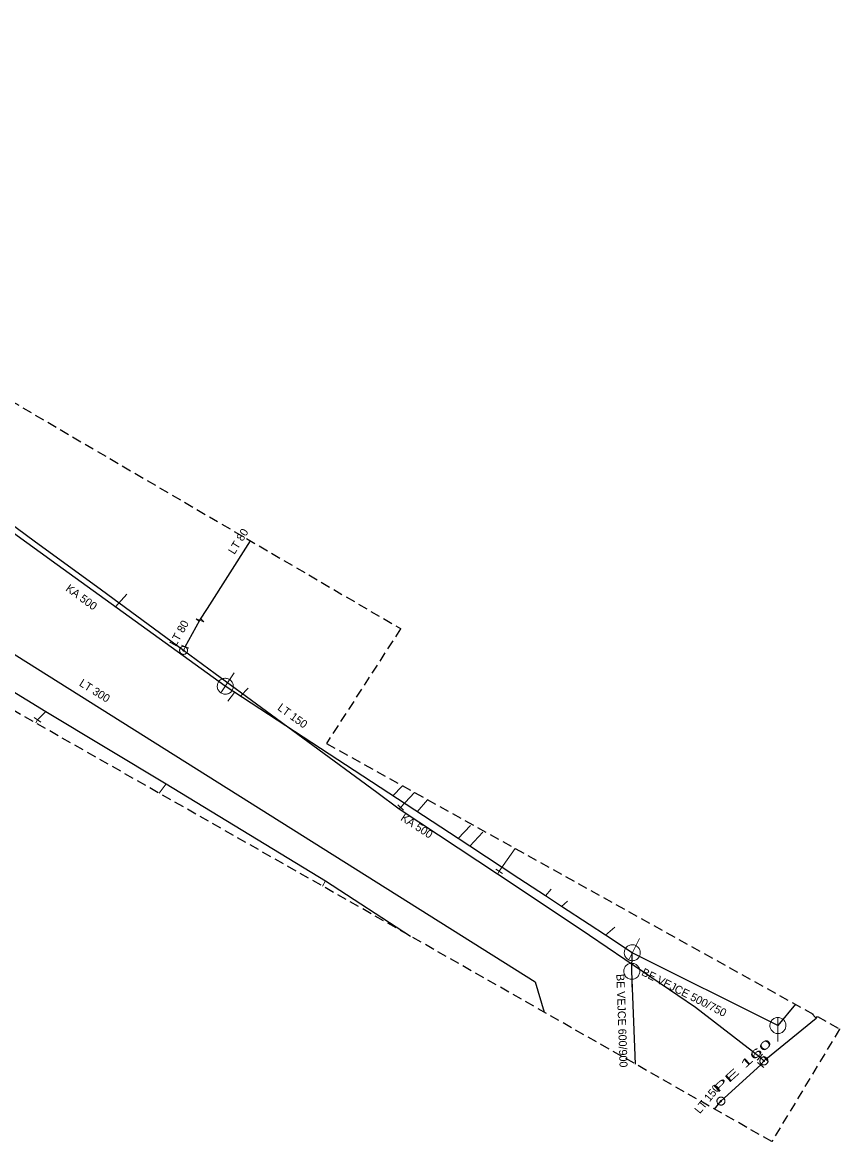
# Model space of a CAD drawing. Extents: x -747112 to -746911, y -964685 to -964545.
# Drawn here: x -747012.7 to -746910.6, y -964684.7 to -964544.9 of the extents above; entities that cross this region are included whole.
import ezdxf

# ---------------------------------------------------------------- set-up
doc = ezdxf.new("R2010")
doc.units = 0
doc.header["$LTSCALE"] = 0.4
doc.linetypes.add('MEDIUM_DASHED', pattern=[4.5, 3, -1.5])
doc.layers.add('1', color=7, linetype='Continuous')
for name, color, linetype, lineweight in [('11', 7, 'Continuous', 13), ('13', 7, 'Continuous', 13), ('14', 7, 'Continuous', 13), ('17', 7, 'Continuous', 25), ('22', 7, 'Continuous', 13), ('34', 7, 'Continuous', 13), ('47', 7, 'Continuous', 13), ('63', 7, 'MEDIUM_DASHED', 25)]:
    doc.layers.add(name, color=color, linetype=linetype, lineweight=lineweight)

msp = doc.modelspace()

# ---------------------------------------------------------------- linework, layer by layer
at = {"layer": '11'}
for p, q in [((-746999.699, -964616.359), (-747001.122, -964617.943)), ((-746987.074, -964629.717), (-746986.216, -964628.62)), ((-746984.513, -964628.107), (-746985.469, -964629.108)), ((-746965.289, -964640.322), (-746966.441, -964641.539)), ((-746962.113, -964642.035), (-746963.4, -964643.526)), ((-746956.714, -964645.237), (-746958.282, -964646.869)), ((-746955.19, -964646.083), (-746956.83, -964647.853)), ((-746946.636, -964653.223), (-746947.368, -964654.028)), ((-746944.605, -964654.714), (-746945.366, -964655.368)), ((-746938.691, -964657.953), (-746939.866, -964658.936))]:
    msp.add_line(p, q, dxfattribs=at)
at = {"layer": '13'}
for p, q in [((-747009.793, -964630.991), (-747010.845, -964632.051)), ((-747010.845, -964632.051), (-747011.081, -964632.441)), ((-746994.776, -964640.041), (-746995.644, -964641.216)), ((-746965.464, -964643.011), (-746963.723, -964641.11)), ((-746974.873, -964652.184), (-746975.215, -964652.828)), ((-746913.524, -964669.316), (-746914.114, -964668.705))]:
    msp.add_line(p, q, dxfattribs=at)
msp.add_lwpolyline([(-746953.369, -964651.351), (-746953.142, -964650.975), (-746951.129, -964648.115)], dxfattribs=at)
at = {"layer": '14'}
for p, q in [((-746992.592, -964623.377), (-746992.399, -964622.915)), ((-746965.631, -964643.226), (-746965.464, -964643.011)), ((-746920.058, -964674.663), (-746920.566, -964674.208)), ((-746920.058, -964674.663), (-746920.46, -964675.157)), ((-746919.813, -964674.445), (-746920.058, -964674.663))]:
    msp.add_line(p, q, dxfattribs=at)
at = {"layer": '14', "lineweight": 25}
for p, q in [((-746918.309, -964670.239), (-746936.511, -964661.149)), ((-746916.123, -964667.588), (-746918.309, -964670.239))]:
    msp.add_line(p, q, dxfattribs=at)
for points in [[(-746987.381, -964627.86), (-746994.138, -964622.982), (-747008.407, -964612.686), (-747020.272, -964604.125), (-747021.16, -964603.609), (-747024.27, -964601.239), (-747027.37, -964599.01), (-747029.581, -964597.407), (-747034.561, -964593.842), (-747037.631, -964591.6)], [(-746936.511, -964661.149), (-746939.866, -964658.936), (-746941.912, -964657.614), (-746945.366, -964655.368), (-746947.368, -964654.028), (-746950.693, -964651.868), (-746956.83, -964647.853), (-746958.282, -964646.869), (-746987.381, -964627.86)], [(-746936.099, -964675.063), (-746936.57, -964663.46), (-746936.511, -964661.149)]]:
    msp.add_lwpolyline(points, dxfattribs=at)
at = {"layer": '17'}
msp.add_line((-746992.399, -964622.915), (-746990.549, -964619.615), dxfattribs=at)
for points in [[(-746992.592, -964623.377), (-747002.848, -964615.868), (-747011.265, -964609.743), (-747020.612, -964602.861), (-747030.192, -964595.879), (-747034.92, -964592.421), (-747039.8, -964588.87), (-747041.949, -964584.539), (-747049.208, -964579.357)], [(-747058.793, -964595.589), (-747057.25, -964596.522), (-746948.662, -964664.784), (-746947.539, -964668.56)], [(-747055.973, -964602.077), (-747028.302, -964619.701), (-747009.793, -964630.991), (-746994.776, -964640.041), (-746974.873, -964652.184), (-746964.215, -964659.081)], [(-746990.549, -964619.615), (-746989.605, -964618.128), (-746984.246, -964609.688)], [(-746920.566, -964674.208), (-746928.627, -964667.991), (-746941.845, -964658.993), (-746949.167, -964654.129), (-746953.369, -964651.351), (-746965.631, -964643.226), (-746968.454, -964641.147), (-746977.079, -964634.796), (-746988.631, -964626.293), (-746992.592, -964623.377)], [(-746919.813, -964674.445), (-746913.524, -964669.316), (-746913.362, -964669.123)], [(-746926.233, -964680.67), (-746925.43, -964679.68), (-746920.46, -964675.157)]]:
    msp.add_lwpolyline(points, dxfattribs=at)
at = {"layer": '22'}
for p, q in [((-746986.286, -964626.185), (-746987.927, -964628.696)), ((-746935.617, -964659.359), (-746936.957, -964662.043)), ((-746936.57, -964665.46), (-746936.569, -964662.46)), ((-746918.309, -964672.239), (-746918.308, -964669.239))]:
    msp.add_line(p, q, dxfattribs=at)
for points in [[(-746988.217, -964627.312), (-746988.272, -964627.407), (-746988.316, -964627.507), (-746988.349, -964627.612), (-746988.371, -964627.719), (-746988.38, -964627.828), (-746988.377, -964627.937), (-746988.363, -964628.046), (-746988.336, -964628.152), (-746988.298, -964628.255), (-746988.25, -964628.353), (-746988.191, -964628.445), (-746988.121, -964628.53), (-746988.043, -964628.607), (-746987.958, -964628.675), (-746987.864, -964628.734), (-746987.766, -964628.781), (-746987.663, -964628.819), (-746987.557, -964628.844), (-746987.448, -964628.857), (-746987.339, -964628.858), (-746987.229, -964628.848), (-746987.123, -964628.825), (-746987.018, -964628.791), (-746986.918, -964628.746), (-746986.824, -964628.69), (-746986.737, -964628.624), (-746986.657, -964628.549), (-746986.586, -964628.466), (-746986.524, -964628.375), (-746986.473, -964628.279), (-746986.432, -964628.178), (-746986.404, -964628.072), (-746986.386, -964627.964), (-746986.38, -964627.854), (-746986.387, -964627.745), (-746986.405, -964627.637), (-746986.435, -964627.532), (-746986.477, -964627.43), (-746986.529, -964627.334), (-746986.592, -964627.244), (-746986.663, -964627.162), (-746986.744, -964627.088), (-746986.832, -964627.022), (-746986.927, -964626.968), (-746987.027, -964626.924), (-746987.131, -964626.891), (-746987.239, -964626.869), (-746987.348, -964626.86), (-746987.458, -964626.862), (-746987.566, -964626.876), (-746987.673, -964626.902), (-746987.775, -964626.941), (-746987.873, -964626.989), (-746987.965, -964627.048), (-746988.05, -964627.117), (-746988.128, -964627.195), (-746988.196, -964627.281)], [(-746937.405, -964660.701), (-746937.448, -964660.801), (-746937.48, -964660.906), (-746937.501, -964661.014), (-746937.51, -964661.123), (-746937.507, -964661.233), (-746937.492, -964661.341), (-746937.464, -964661.447), (-746937.426, -964661.549), (-746937.377, -964661.648), (-746937.317, -964661.739), (-746937.248, -964661.824), (-746937.169, -964661.9), (-746937.083, -964661.968), (-746936.99, -964662.025), (-746936.89, -964662.073), (-746936.788, -964662.108), (-746936.681, -964662.134), (-746936.572, -964662.147), (-746936.462, -964662.147), (-746936.354, -964662.136), (-746936.246, -964662.113), (-746936.143, -964662.078), (-746936.043, -964662.032), (-746935.949, -964661.976), (-746935.862, -964661.91), (-746935.783, -964661.834), (-746935.712, -964661.75), (-746935.651, -964661.66), (-746935.6, -964661.562), (-746935.561, -964661.46), (-746935.532, -964661.355), (-746935.516, -964661.247), (-746935.51, -964661.138), (-746935.517, -964661.028), (-746935.537, -964660.92), (-746935.567, -964660.815), (-746935.609, -964660.714), (-746935.662, -964660.618), (-746935.725, -964660.529), (-746935.798, -964660.446), (-746935.878, -964660.373), (-746935.967, -964660.308), (-746936.063, -964660.254), (-746936.163, -964660.211), (-746936.267, -964660.178), (-746936.374, -964660.157), (-746936.484, -964660.149), (-746936.594, -964660.152), (-746936.702, -964660.167), (-746936.808, -964660.193), (-746936.911, -964660.231), (-746937.008, -964660.281), (-746937.101, -964660.34), (-746937.185, -964660.41), (-746937.261, -964660.488), (-746937.329, -964660.575), (-746937.387, -964660.668)], [(-746935.57, -964663.46), (-746935.575, -964663.351), (-746935.593, -964663.243), (-746935.623, -964663.137), (-746935.663, -964663.036), (-746935.715, -964662.939), (-746935.777, -964662.849), (-746935.849, -964662.766), (-746935.929, -964662.692), (-746936.017, -964662.626), (-746936.111, -964662.571), (-746936.211, -964662.526), (-746936.316, -964662.493), (-746936.423, -964662.471), (-746936.532, -964662.461), (-746936.642, -964662.463), (-746936.75, -964662.477), (-746936.857, -964662.502), (-746936.96, -964662.539), (-746937.058, -964662.588), (-746937.15, -964662.646), (-746937.236, -964662.715), (-746937.313, -964662.792), (-746937.382, -964662.878), (-746937.441, -964662.97), (-746937.489, -964663.068), (-746937.526, -964663.171), (-746937.552, -964663.278), (-746937.566, -964663.386), (-746937.569, -964663.496), (-746937.559, -964663.605), (-746937.538, -964663.712), (-746937.504, -964663.816), (-746937.46, -964663.916), (-746937.405, -964664.011), (-746937.339, -964664.099), (-746937.265, -964664.179), (-746937.182, -964664.251), (-746937.092, -964664.313), (-746936.996, -964664.365), (-746936.894, -964664.406), (-746936.789, -964664.436), (-746936.681, -964664.454), (-746936.571, -964664.46), (-746936.462, -964664.454), (-746936.354, -964664.436), (-746936.249, -964664.407), (-746936.147, -964664.366), (-746936.05, -964664.314), (-746935.96, -964664.252), (-746935.877, -964664.181), (-746935.802, -964664.101), (-746935.737, -964664.013), (-746935.681, -964663.919), (-746935.637, -964663.819), (-746935.603, -964663.715), (-746935.581, -964663.607), (-746935.571, -964663.498)], [(-746917.309, -964670.239), (-746917.314, -964670.13), (-746917.332, -964670.022), (-746917.362, -964669.916), (-746917.402, -964669.815), (-746917.454, -964669.718), (-746917.516, -964669.628), (-746917.588, -964669.545), (-746917.668, -964669.471), (-746917.756, -964669.405), (-746917.85, -964669.35), (-746917.95, -964669.305), (-746918.055, -964669.272), (-746918.162, -964669.25), (-746918.271, -964669.24), (-746918.381, -964669.242), (-746918.489, -964669.256), (-746918.596, -964669.281), (-746918.699, -964669.318), (-746918.797, -964669.367), (-746918.889, -964669.425), (-746918.975, -964669.494), (-746919.052, -964669.571), (-746919.121, -964669.657), (-746919.18, -964669.749), (-746919.228, -964669.847), (-746919.265, -964669.95), (-746919.291, -964670.057), (-746919.305, -964670.165), (-746919.308, -964670.275), (-746919.298, -964670.384), (-746919.277, -964670.491), (-746919.243, -964670.595), (-746919.199, -964670.695), (-746919.144, -964670.79), (-746919.078, -964670.878), (-746919.004, -964670.958), (-746918.921, -964671.03), (-746918.831, -964671.092), (-746918.735, -964671.144), (-746918.633, -964671.185), (-746918.528, -964671.215), (-746918.42, -964671.233), (-746918.31, -964671.239), (-746918.201, -964671.233), (-746918.093, -964671.215), (-746917.988, -964671.186), (-746917.886, -964671.145), (-746917.789, -964671.093), (-746917.699, -964671.031), (-746917.616, -964670.96), (-746917.541, -964670.88), (-746917.476, -964670.792), (-746917.42, -964670.698), (-746917.376, -964670.598), (-746917.342, -964670.494), (-746917.32, -964670.386), (-746917.31, -964670.277)]]:
    msp.add_lwpolyline(points, close=True, dxfattribs=at)
at = {"layer": '34'}
for p, q in [((-746992.86, -964622.722), (-746991.937, -964623.108)), ((-747011.264, -964631.779), (-747010.425, -964632.323)), ((-746965.833, -964642.673), (-746965.095, -964643.349)), ((-746953.551, -964650.687), (-746952.733, -964651.263)), ((-746920.899, -964674.58), (-746920.231, -964673.835)), ((-746920.852, -964674.847), (-746920.068, -964675.467)), ((-746920.129, -964674.057), (-746919.497, -964674.832))]:
    msp.add_line(p, q, dxfattribs=at)
at = {"layer": '47'}
msp.add_line((-746991.023, -964619.429), (-746990.656, -964619.784), dxfattribs=at)
msp.add_lwpolyline([(-746991.023, -964619.429), (-746990.074, -964619.8), (-746990.441, -964619.445)], dxfattribs=at)
for points in [[(-746992.994, -964623.08), (-746993.023, -964623.124), (-746993.047, -964623.17), (-746993.065, -964623.219), (-746993.08, -964623.269), (-746993.088, -964623.321), (-746993.091, -964623.374), (-746993.088, -964623.426), (-746993.08, -964623.477), (-746993.068, -964623.528), (-746993.05, -964623.577), (-746993.026, -964623.624), (-746992.997, -964623.668), (-746992.965, -964623.709), (-746992.928, -964623.746), (-746992.888, -964623.779), (-746992.844, -964623.808), (-746992.798, -964623.832), (-746992.748, -964623.851), (-746992.699, -964623.865), (-746992.647, -964623.873), (-746992.594, -964623.876), (-746992.542, -964623.874), (-746992.49, -964623.866), (-746992.44, -964623.853), (-746992.391, -964623.835), (-746992.344, -964623.811), (-746992.299, -964623.783), (-746992.259, -964623.75), (-746992.222, -964623.713), (-746992.189, -964623.673), (-746992.16, -964623.629), (-746992.136, -964623.583), (-746992.116, -964623.534), (-746992.103, -964623.484), (-746992.095, -964623.432), (-746992.091, -964623.38), (-746992.093, -964623.327), (-746992.101, -964623.276), (-746992.115, -964623.225), (-746992.133, -964623.176), (-746992.157, -964623.129), (-746992.184, -964623.085), (-746992.218, -964623.044), (-746992.255, -964623.007), (-746992.295, -964622.974), (-746992.339, -964622.945), (-746992.385, -964622.921), (-746992.433, -964622.902), (-746992.484, -964622.888), (-746992.536, -964622.88), (-746992.588, -964622.876), (-746992.64, -964622.879), (-746992.692, -964622.887), (-746992.743, -964622.9), (-746992.792, -964622.918), (-746992.839, -964622.942), (-746992.882, -964622.97), (-746992.924, -964623.003), (-746992.961, -964623.04)], [(-746992.658, -964623.328), (-746992.663, -964623.335), (-746992.666, -964623.343), (-746992.669, -964623.35), (-746992.671, -964623.359), (-746992.673, -964623.367), (-746992.673, -964623.376), (-746992.673, -964623.385), (-746992.672, -964623.393), (-746992.669, -964623.401), (-746992.667, -964623.409), (-746992.663, -964623.417), (-746992.658, -964623.424), (-746992.653, -964623.431), (-746992.647, -964623.437), (-746992.64, -964623.443), (-746992.633, -964623.448), (-746992.625, -964623.451), (-746992.618, -964623.454), (-746992.609, -964623.456), (-746992.601, -964623.458), (-746992.592, -964623.458), (-746992.583, -964623.458), (-746992.575, -964623.457), (-746992.566, -964623.455), (-746992.559, -964623.452), (-746992.551, -964623.448), (-746992.544, -964623.443), (-746992.537, -964623.438), (-746992.531, -964623.432), (-746992.525, -964623.425), (-746992.52, -964623.418), (-746992.517, -964623.41), (-746992.514, -964623.403), (-746992.512, -964623.394), (-746992.51, -964623.386), (-746992.509, -964623.378), (-746992.51, -964623.368), (-746992.511, -964623.36), (-746992.513, -964623.351), (-746992.516, -964623.344), (-746992.52, -964623.336), (-746992.525, -964623.329), (-746992.53, -964623.322), (-746992.536, -964623.316), (-746992.543, -964623.31), (-746992.55, -964623.305), (-746992.558, -964623.302), (-746992.565, -964623.299), (-746992.574, -964623.297), (-746992.582, -964623.295), (-746992.59, -964623.294), (-746992.6, -964623.295), (-746992.608, -964623.296), (-746992.616, -964623.299), (-746992.624, -964623.301), (-746992.632, -964623.305), (-746992.639, -964623.31), (-746992.646, -964623.315), (-746992.652, -964623.321)], [(-746920.432, -964674.994), (-746920.395, -964675.031), (-746920.354, -964675.065), (-746920.311, -964675.093), (-746920.265, -964675.118), (-746920.216, -964675.137), (-746920.165, -964675.151), (-746920.113, -964675.159), (-746920.061, -964675.162), (-746920.009, -964675.16), (-746919.957, -964675.152), (-746919.906, -964675.139), (-746919.858, -964675.12), (-746919.811, -964675.097), (-746919.767, -964675.069), (-746919.726, -964675.037), (-746919.689, -964675), (-746919.655, -964674.959), (-746919.626, -964674.915), (-746919.602, -964674.87), (-746919.583, -964674.821), (-746919.569, -964674.77), (-746919.561, -964674.718), (-746919.558, -964674.666), (-746919.559, -964674.614), (-746919.568, -964674.562), (-746919.581, -964674.511), (-746919.599, -964674.462), (-746919.623, -964674.416), (-746919.651, -964674.372), (-746919.683, -964674.331), (-746919.72, -964674.294), (-746919.761, -964674.26), (-746919.804, -964674.231), (-746919.85, -964674.207), (-746919.899, -964674.188), (-746919.95, -964674.174), (-746920.001, -964674.165), (-746920.054, -964674.162), (-746920.106, -964674.164), (-746920.158, -964674.173), (-746920.209, -964674.186), (-746920.257, -964674.204), (-746920.304, -964674.228), (-746920.348, -964674.256), (-746920.389, -964674.288), (-746920.426, -964674.325), (-746920.46, -964674.366), (-746920.489, -964674.409), (-746920.513, -964674.455), (-746920.532, -964674.504), (-746920.546, -964674.555), (-746920.554, -964674.606), (-746920.557, -964674.658), (-746920.555, -964674.711), (-746920.547, -964674.763), (-746920.534, -964674.814), (-746920.516, -964674.862), (-746920.492, -964674.909), (-746920.464, -964674.953)], [(-746920.119, -964674.717), (-746920.113, -964674.724), (-746920.106, -964674.728), (-746920.099, -964674.733), (-746920.092, -964674.737), (-746920.083, -964674.74), (-746920.075, -964674.742), (-746920.067, -964674.744), (-746920.058, -964674.745), (-746920.05, -964674.744), (-746920.041, -964674.743), (-746920.032, -964674.741), (-746920.024, -964674.737), (-746920.017, -964674.734), (-746920.01, -964674.73), (-746920.003, -964674.724), (-746919.996, -964674.718), (-746919.992, -964674.711), (-746919.987, -964674.704), (-746919.983, -964674.697), (-746919.98, -964674.688), (-746919.978, -964674.68), (-746919.976, -964674.672), (-746919.975, -964674.663), (-746919.976, -964674.654), (-746919.977, -964674.646), (-746919.979, -964674.637), (-746919.983, -964674.629), (-746919.986, -964674.622), (-746919.99, -964674.615), (-746919.996, -964674.608), (-746920.002, -964674.601), (-746920.009, -964674.597), (-746920.016, -964674.592), (-746920.023, -964674.588), (-746920.032, -964674.585), (-746920.039, -964674.582), (-746920.048, -964674.581), (-746920.057, -964674.58), (-746920.066, -964674.581), (-746920.074, -964674.582), (-746920.083, -964674.584), (-746920.091, -964674.588), (-746920.098, -964674.591), (-746920.105, -964674.595), (-746920.112, -964674.601), (-746920.119, -964674.607), (-746920.123, -964674.614), (-746920.128, -964674.621), (-746920.132, -964674.628), (-746920.135, -964674.637), (-746920.138, -964674.644), (-746920.139, -964674.653), (-746920.14, -964674.662), (-746920.139, -964674.67), (-746920.138, -964674.679), (-746920.136, -964674.688), (-746920.132, -964674.696), (-746920.129, -964674.703), (-746920.125, -964674.71)], [(-746925.002, -964679.938), (-746924.977, -964679.892), (-746924.957, -964679.844), (-746924.943, -964679.794), (-746924.933, -964679.742), (-746924.93, -964679.69), (-746924.932, -964679.637), (-746924.939, -964679.586), (-746924.952, -964679.535), (-746924.969, -964679.486), (-746924.991, -964679.439), (-746925.019, -964679.394), (-746925.052, -964679.353), (-746925.087, -964679.315), (-746925.128, -964679.281), (-746925.171, -964679.252), (-746925.217, -964679.227), (-746925.265, -964679.207), (-746925.316, -964679.193), (-746925.367, -964679.183), (-746925.419, -964679.18), (-746925.472, -964679.182), (-746925.524, -964679.189), (-746925.575, -964679.201), (-746925.624, -964679.218), (-746925.67, -964679.241), (-746925.715, -964679.269), (-746925.757, -964679.301), (-746925.794, -964679.337), (-746925.828, -964679.378), (-746925.857, -964679.421), (-746925.882, -964679.467), (-746925.902, -964679.515), (-746925.917, -964679.566), (-746925.926, -964679.617), (-746925.929, -964679.669), (-746925.928, -964679.721), (-746925.921, -964679.773), (-746925.909, -964679.824), (-746925.891, -964679.874), (-746925.868, -964679.92), (-746925.84, -964679.965), (-746925.809, -964680.006), (-746925.772, -964680.044), (-746925.731, -964680.078), (-746925.688, -964680.107), (-746925.642, -964680.132), (-746925.594, -964680.152), (-746925.544, -964680.166), (-746925.492, -964680.176), (-746925.44, -964680.179), (-746925.388, -964680.178), (-746925.336, -964680.171), (-746925.286, -964680.158), (-746925.236, -964680.14), (-746925.189, -964680.118), (-746925.144, -964680.09), (-746925.103, -964680.058), (-746925.065, -964680.022), (-746925.031, -964679.981)], [(-746925.359, -964679.722), (-746925.355, -964679.714), (-746925.352, -964679.706), (-746925.35, -964679.699), (-746925.348, -964679.69), (-746925.348, -964679.681), (-746925.348, -964679.673), (-746925.349, -964679.664), (-746925.351, -964679.656), (-746925.354, -964679.648), (-746925.358, -964679.64), (-746925.362, -964679.632), (-746925.368, -964679.626), (-746925.374, -964679.62), (-746925.379, -964679.614), (-746925.387, -964679.609), (-746925.395, -964679.605), (-746925.403, -964679.602), (-746925.41, -964679.6), (-746925.419, -964679.598), (-746925.428, -964679.598), (-746925.436, -964679.598), (-746925.445, -964679.599), (-746925.453, -964679.601), (-746925.462, -964679.604), (-746925.469, -964679.608), (-746925.477, -964679.612), (-746925.483, -964679.618), (-746925.489, -964679.624), (-746925.495, -964679.629), (-746925.5, -964679.637), (-746925.504, -964679.645), (-746925.507, -964679.653), (-746925.509, -964679.66), (-746925.511, -964679.669), (-746925.511, -964679.678), (-746925.512, -964679.686), (-746925.51, -964679.695), (-746925.508, -964679.703), (-746925.505, -964679.712), (-746925.501, -964679.719), (-746925.497, -964679.727), (-746925.491, -964679.733), (-746925.485, -964679.739), (-746925.48, -964679.745), (-746925.472, -964679.75), (-746925.464, -964679.754), (-746925.456, -964679.757), (-746925.449, -964679.759), (-746925.44, -964679.761), (-746925.431, -964679.761), (-746925.423, -964679.762), (-746925.414, -964679.76), (-746925.406, -964679.758), (-746925.398, -964679.755), (-746925.39, -964679.751), (-746925.382, -964679.747), (-746925.376, -964679.741), (-746925.37, -964679.735), (-746925.364, -964679.73)]]:
    msp.add_lwpolyline(points, close=True, dxfattribs=at)
at = {"layer": '63'}
msp.add_lwpolyline([(-747095.047, -964544.929), (-746965.47, -964620.662), (-746965.468, -964620.663), (-746965.467, -964620.664), (-746965.466, -964620.666), (-746965.465, -964620.668), (-746965.465, -964620.67), (-746965.465, -964620.672), (-746965.466, -964620.674), (-746965.467, -964620.676), (-746974.726, -964634.99), (-746910.599, -964670.66), (-746910.597, -964670.661), (-746910.596, -964670.663), (-746910.595, -964670.665), (-746910.594, -964670.666), (-746910.594, -964670.668), (-746910.594, -964670.67), (-746910.594, -964670.672), (-746910.595, -964670.674), (-746919.063, -964684.735), (-746919.064, -964684.737), (-746919.065, -964684.738), (-746919.067, -964684.739), (-746919.069, -964684.74), (-746919.071, -964684.74), (-746919.073, -964684.74), (-746919.074, -964684.74), (-746919.076, -964684.739), (-747112.263, -964574.928)], dxfattribs=at)

# ---------------------------------------------------------------- texts
at = {"layer": '1'}
for s, rotation, p in [('LT 80 ', 58, (-746986.243, -964611.467)), ('KA 500', 324, (-747007.42, -964615.846)), ('LT 80 ', 61, (-746993.556, -964622.964)), ('LT 300', 328, (-747005.726, -964627.729)), ('LT 150', 324, (-746980.942, -964630.729)), ('KA 500', 327, (-746965.549, -964644.532)), ('BE VEJCE 500/750', 333, (-746935.454, -964663.895)), ('BE VEJCE 600/900', 272, (-746938.5, -964663.818)), ('LT 150', 51, (-746928.061, -964681.332))]:
    msp.add_text(s, height=1, rotation=rotation, dxfattribs=at).set_placement(p)
at = {"layer": '1', "width": 2.1}
msp.add_text('PE 160', height=1, rotation=42, dxfattribs=at).set_placement((-746925.827, -964678.709))

doc.saveas('drawing.dxf')
